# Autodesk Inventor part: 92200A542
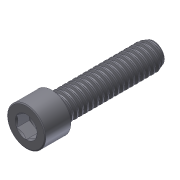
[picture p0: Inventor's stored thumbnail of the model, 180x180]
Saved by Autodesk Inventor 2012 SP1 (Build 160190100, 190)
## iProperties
Created: 2012-02
Part Number: 92200A542
Material: Stainless Steel
Document SubType Name: Modeling
Designer: LACO
Density: 8.08 g/cm^3
Mass: 8.57925 g
Surface Area: 10.5217 cm^2
Volume: 1.06179 cm^3
Translation Standard: STEP AP203
FileName: 92200A542.step
PreProcessor: SolidWorks 2003314
PostProcessor: Build: 190, Release: 2012 SP1 - Date: Mon 08/08/2011
Sent Units: inch
Uncertainty: 1e-05
Author: LACO
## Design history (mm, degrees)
node "92200A5421"
node "NONE"
node "Base1"
